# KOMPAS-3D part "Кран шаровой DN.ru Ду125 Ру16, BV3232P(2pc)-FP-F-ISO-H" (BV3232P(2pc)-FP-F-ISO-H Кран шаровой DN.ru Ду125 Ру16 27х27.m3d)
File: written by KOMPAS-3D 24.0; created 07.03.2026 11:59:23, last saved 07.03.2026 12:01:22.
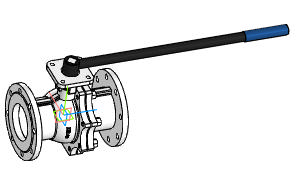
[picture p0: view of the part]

Document properties: Автор: R2D2; Полное имя файла: BV3232P(2pc)-FP-F-ISO-H Кран шаровой DN.ru Ду125 Ру16.cdw

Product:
- Part/product: Кран шаровой DN.ru Ду125 Ру16  | designation BV3232P(2pc)-FP-F-ISO-H
    Масса: 32
    Раздел спецификации: Прочие изделия
    Форматы листов документа: A2
    Примечание: D160-22160

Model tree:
1. Операция без истории:1

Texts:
  BV3232P(2pc)-FP-F-ISO-H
